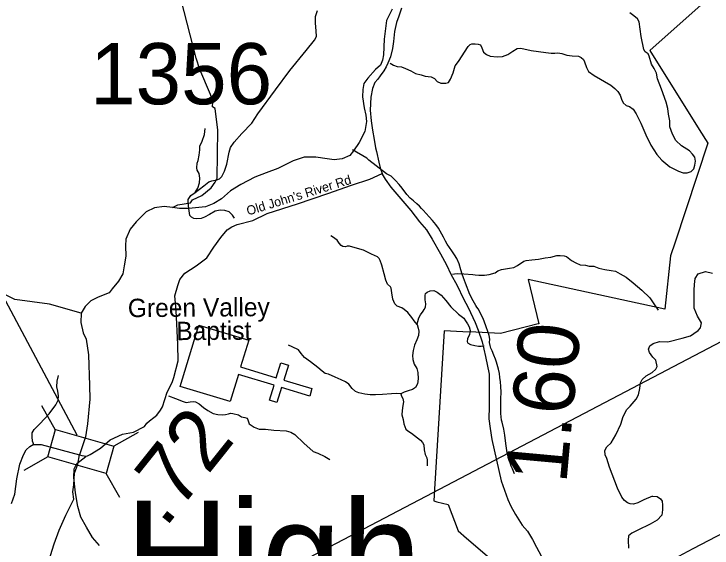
# Model space of a CAD drawing. Extents: x 1159738 to 1321356, y 736314 to 882035.
# Drawn here: x 1204145 to 1209848, y 819333 to 823694 of the extents above; entities that cross this region are included whole.
import ezdxf

# ---------------------------------------------------------------- set-up
doc = ezdxf.new("R2010")
doc.units = 0
for name, color, linetype in [('Exist Boundary Land Use Forest National US Forest Service', 7, 'Continuous'), ('Exist Cultural Church CELL', 7, 'Continuous'), ('Exist Cultural Church Label', 7, 'Continuous'), ('Exist Geographical Mountain Summit Label', 7, 'Continuous'), ('Exist Hydrographic Creek Single Shore', 7, 'Continuous'), ('Exist Hydrographic Misc Water Feature', 7, 'Continuous'), ('Exist Road Non-System Type 51', 7, 'Continuous'), ('Exist Road Primary NC Attributed', 7, 'Continuous'), ('Exist Road Primary NC Mileage Hundredths English Label', 7, 'Continuous'), ('Exist Road Secondary Mileage Hundredths English Label', 7, 'Continuous'), ('Exist Road Secondary Structure Standard Bridge CELL', 7, 'Continuous'), ('Exist Road Secondary Structure Standard Bridge Number Label', 7, 'Continuous'), ('Exist Road Secondary Type 51 Attributed', 7, 'Continuous'), ('Exist Road Secondary Type 51 Label', 7, 'Continuous'), ('Exist Road Secondary Type 51 Number Label', 7, 'Continuous')]:
    doc.layers.add(name, color=color, linetype=linetype)

msp = doc.modelspace()

# ---------------------------------------------------------------- linework, layer by layer
at = {"layer": 'Exist Boundary Land Use Forest National US Forest Service'}
for points in [[(1210716.8, 824624), (1209339.9, 823397), (1209742.6, 822750.6), (1209812.8, 822637.9), (1209546.9, 821832), (1209509.9, 821719.9), (1209462.9, 821285), (1208344.9, 821524.9), (1208432.8, 821164.9), (1208427.3, 821163.4), (1208120.8, 821084.9), (1208021.4, 821089.7), (1207917.7, 821094.8), (1207810.9, 821099.9), (1207658.9, 821107.9), (1207581.8, 819815.4), (1207575.9, 819717.9), (1207599, 819712), (1207692.9, 819687.9), (1207774.9, 819473.9), (1207843.5, 819414.6), (1208048.9, 819236.9)], [(1207696, 817082.7), (1207724.8, 817404.2), (1207856.8, 818877.8), (1208591.1, 818865.7), (1208749.2, 818863), (1208822.8, 818861.8), (1209283.9, 819106.9), (1209342.2, 819138.6), (1209612.9, 819285.9), (1209694.2, 819328.4), (1210211.4, 819598.8)]]:
    msp.add_lwpolyline(points, dxfattribs=at)
at = {"layer": 'Exist Cultural Church CELL'}
msp.add_lwpolyline([(1206062.7, 821029.8), (1205997.1, 820811.7), (1206288.6, 820723.4), (1206325.7, 820845.9), (1206386.9, 820827.4), (1206349.8, 820704.9), (1206580, 820635.1), (1206561.4, 820573.8), (1206331.2, 820643.5), (1206294.1, 820521), (1206232.9, 820539.6), (1206270, 820662.1), (1205978.5, 820750.4), (1205911.2, 820529.8), (1205503.7, 820653.3), (1205655.2, 821153.3)], close=True, dxfattribs=at)
at = {"layer": 'Exist Hydrographic Creek Single Shore'}
for points in [[(1207233.9, 823732.7), (1207188, 823640.6), (1207170.9, 823487.3), (1207164.1, 823361.2), (1207155.6, 823316.9), (1207138.6, 823276), (1207097.7, 823240.2), (1207036.4, 823168.6), (1207004, 823126), (1206995.5, 823076.6), (1206993.8, 823016.9), (1207005.7, 822926.6), (1207021.2, 822866.7), (1207026.3, 822817.3), (1207011, 822735.5), (1206966.7, 822645.1), (1206919.1, 822577), (1206888.4, 822537.8), (1206827.1, 822510.5), (1206762.4, 822502), (1206704.5, 822510.5), (1206610.8, 822524.1), (1206517.2, 822525.9), (1206425.2, 822495.2), (1206300.9, 822432.1), (1206206.6, 822396.9), (1206113, 822361.1), (1205998.9, 822301.5), (1205915.4, 822248.7), (1205840.5, 822183.9), (1205777.5, 822146.4), (1205711.1, 822119.1), (1205574.8, 822105.5)], [(1205574.8, 822105.5), (1205497, 822105.3), (1205441.8, 822115), (1205373.6, 822121.5), (1205292.4, 822111.8), (1205224.2, 822079.3), (1205143, 821998), (1205094.3, 821936.3), (1205058.6, 821855), (1205055.3, 821799.8), (1205058.6, 821715.3), (1205045.6, 821637.3), (1205035.8, 821572.3), (1205000.1, 821513.7), (1204948.1, 821448.7), (1204922.2, 821416.2), (1204834.5, 821380.5), (1204772.8, 821351.2), (1204727.3, 821305.7), (1204694.4, 821251.6), (1204691.6, 821175.7), (1204711, 821091.2), (1204735.4, 821038.4), (1204753.3, 820910), (1204761.4, 820659.7), (1204764.6, 820547.6), (1204746.7, 820347.1), (1204730.5, 820241.4), (1204681.5, 820094.2)], [(1204053.6, 819113.7), (1204147.4, 819103.5), (1204230.1, 819068.8), (1204295.3, 819079), (1204364.6, 819132), (1204413.5, 819198.9), (1204444.1, 819272.3), (1204472.6, 819368.2), (1204513.4, 819480.3), (1204570.4, 819602.7), (1204633.6, 819733.2), (1204625.4, 819793.3), (1204635.6, 819850.4), (1204639.6, 819944.2), (1204666.1, 820018.3), (1204681.5, 820094.2)]]:
    msp.add_lwpolyline(points, dxfattribs=at)
at = {"layer": 'Exist Hydrographic Misc Water Feature'}
for points in [[(1205441.8, 822115), (1205484.3, 822134.4), (1205588, 822150.8), (1205604.3, 822176.2), (1205678.9, 822212.6), (1205755.2, 822274.5), (1205789.8, 822321.8), (1205804.3, 822354.5), (1205811.6, 822745.7), (1205789.7, 822921.1), (1205766.1, 822935.7), (1205769.7, 822973.9), (1205749.7, 823037.6), (1205663.8, 823239.8), (1205632.7, 823332.3), (1205436.7, 824097.8)], [(1204694.4, 821251.6), (1204435.7, 821324.3), (1204153.8, 821362.8), (1204005.8, 821434.7), (1203729.8, 821715.9), (1203302.7, 821970.7), (1203205.7, 822058), (1203127.7, 822266.3), (1203044.8, 822612.7), (1202809.7, 822834), (1202611.7, 822923.4), (1202538.7, 823010.2), (1202508.8, 823125.7), (1202421.7, 823311.2), (1202283.7, 823740.7)], [(1208234.5, 819939.7), (1208228.9, 819953.8), (1208217.6, 819980.1), (1208208.3, 820002.4), (1208198.9, 820028.7), (1208191.5, 820048.9), (1208186, 820067.1), (1208173.1, 820109.4), (1208163.1, 820185.7), (1208155, 820256), (1208146.4, 820304.3), (1208133.9, 820360.7), (1208128.3, 820378.8), (1208121.8, 820433.1), (1208123.4, 820493), (1208123, 820551.1), (1208124.5, 820607.1), (1208121.8, 820653.2), (1208118.7, 820689.3), (1208113.8, 820725.5), (1208112.6, 820757.5), (1208103.5, 820793.8), (1208087, 820850.2), (1208077.8, 820876.5), (1208064.7, 820908.9), (1208051.4, 820943.3), (1208042.1, 820965.6), (1208034.7, 820987.8), (1208031.3, 821011.9), (1208032.1, 821039.9), (1208026.8, 821068.1), (1208019.6, 821094.3), (1208001, 821146.9), (1207978.6, 821207.4), (1207936.7, 821286.7), (1207927.1, 821300.9), (1207917.4, 821313.2), (1207896.5, 821351.8), (1207869.9, 821404.6), (1207834.4, 821495.5), (1207817.5, 821540), (1207806.3, 821570.3), (1207795.2, 821604.7), (1207782.6, 821655.1), (1207763.7, 821697.6), (1207744.6, 821728.2), (1207723.3, 821760.7), (1207704.1, 821787.3), (1207684.8, 821815.8), (1207669.4, 821840.2), (1207654.3, 821872.7), (1207612.3, 821943.8), (1207591.1, 821974.5), (1207563.9, 822007.3), (1207536.6, 822038), (1207488.2, 822091.4), (1207474.6, 822105.7), (1207459, 822124.2), (1207437.6, 822144.7), (1207410.2, 822167.5), (1207380.8, 822190.3), (1207355.6, 822219), (1207316.9, 822272.1), (1207291.7, 822302.8), (1207262.6, 822333.6), (1207246.9, 822350.1), (1207225.5, 822368.6), (1207203.8, 822381.2), (1207188, 822387.7), (1207045.4, 822499.2), (1207027.9, 822517.7), (1206911.1, 822585.3), (1206911.1, 822585.3)]]:
    msp.add_lwpolyline(points, dxfattribs=at)
at = {"layer": 'Exist Road Non-System Type 51'}
for points in [[(1205624.3, 822236.2), (1205696.8, 822289.7), (1205738.6, 822322.5), (1205762.2, 822331.6), (1205802.2, 822340.7), (1205824, 822347.9), (1205842.2, 822368), (1205864, 822409.8), (1205884, 822468), (1205902.2, 822564.5), (1205914.9, 822604.5), (1205944, 822648.1), (1206007.7, 822717.3), (1206089.5, 822802.8), (1206136.8, 822877.4), (1206281.9, 823074.6), (1206398.3, 823231.1), (1206532.8, 823396.6), (1206600.1, 823479.4), (1206616.4, 823510.4), (1206614.6, 823555.8), (1206609.1, 823617.7), (1206609.1, 823672.3), (1206625.5, 823723.2)], [(1207218.8, 823291.8), (1207245.5, 823276.2), (1207276.7, 823265), (1207310.1, 823262.8), (1207343.5, 823248.3), (1207388.1, 823230.5), (1207425.9, 823208.2), (1207472.7, 823197.1), (1207505, 823185.9), (1207552.9, 823181.5), (1207579.6, 823167), (1207603, 823143.6), (1207633.1, 823129.1), (1207673.2, 823130.2), (1207695.4, 823135.8), (1207712.1, 823161.4), (1207732.2, 823213.8), (1207750, 823269.5), (1207775.6, 823305.2), (1207856.9, 823428.9), (1207872, 823445.4), (1207885.3, 823451), (1207898.7, 823451), (1207912.1, 823451), (1207936.6, 823448.8), (1207955.5, 823443.2), (1207967.7, 823418.7), (1207981.1, 823383), (1208004.5, 823361.8), (1208036.8, 823348.5), (1208091.4, 823345.1), (1208137, 823347.4), (1208180.4, 823363), (1208219.4, 823390.8), (1208257.3, 823413.1), (1208286.2, 823414.2), (1208370.9, 823396.4), (1208490, 823378.6), (1208532.7, 823374.1), (1208563.9, 823375.2), (1208587.3, 823376.3), (1208621.8, 823370.7), (1208661.9, 823358.5), (1208706.4, 823351.8), (1208757.6, 823348.4), (1208779.9, 823339.5), (1208797.7, 823322.8), (1208806.6, 823303.9), (1208823.3, 823255.9), (1208840.1, 823223.6), (1208885.7, 823192.4), (1209021.6, 823113.3), (1209053.6, 823085.9), (1209078.1, 823061.4), (1209098.2, 823030.2), (1209108.2, 822999), (1209121.6, 822967.8), (1209146.1, 822947.7), (1209175, 822937.7), (1209204, 822916.5), (1209227.4, 822878.7), (1209267.3, 822802.3), (1209306.3, 822707.5), (1209348.6, 822623.9), (1209396.5, 822545.9), (1209437.7, 822499.1), (1209504.5, 822446.8), (1209574.6, 822410.1), (1209613.5, 822396.8), (1209645.8, 822396.8), (1209677, 822407.9), (1209698.2, 822430.2), (1209708.2, 822460.3), (1209712.6, 822492.6), (1209707.1, 822526), (1209689.3, 822548.3), (1209663.6, 822577.3), (1209597.9, 822618.5), (1209553.4, 822662), (1209525.6, 822713.3), (1209503.3, 822772.3), (1209504.4, 822821.4), (1209492.1, 822876), (1209487.7, 822921.6), (1209472.1, 822975.1), (1209434.4, 823079), (1209403.2, 823163.7), (1209393.2, 823211.6), (1209375.3, 823249.5), (1209354.2, 823284), (1209335.3, 823348.7), (1209326.3, 823369.8), (1209303, 823385.4), (1209289.6, 823404.4), (1209268.4, 823510.2), (1209252.9, 823631), (1209238.4, 823653.3), (1209209.4, 823678.9), (1209176, 823703.4)], [(1205946.1, 822027), (1205929.8, 822052.5), (1205904.3, 822077.9), (1205867.9, 822088.9), (1205829.8, 822092.5), (1205789.8, 822085.2), (1205742.5, 822057.9), (1205700.7, 822034.3), (1205673.4, 822023.4), (1205635.2, 822021.5), (1205615.2, 822023.4), (1205597, 822034.3), (1205582.5, 822048.8), (1205574.8, 822105.5), (1205569.8, 822156.2), (1205567.9, 822178), (1205589.8, 822210.8), (1205624.3, 822236.2), (1205646.1, 822272.6), (1205660.7, 822316.3), (1205662.5, 822354.5), (1205657, 822390.9), (1205642.5, 822418.2), (1205638.9, 822436.4), (1205640.7, 822474.6), (1205649.8, 822498.2), (1205658.9, 822541.9), (1205664.3, 822585.6), (1205664.3, 822614.7), (1205682.5, 822656.5), (1205700.7, 822711.1), (1205707.9, 822760.2)], [(1207439.7, 821158.9), (1207414.5, 821188.2), (1207396.3, 821215.9), (1207363.2, 821257), (1207333.9, 821282.3), (1207313.4, 821294.1), (1207274.7, 821309.2), (1207256.5, 821326.6), (1207240.7, 821364.5), (1207231.7, 821416.1), (1207227, 821454.9), (1207221.5, 821465.2), (1207196.2, 821488.9), (1207182.7, 821520.5), (1207170.9, 821572.7), (1207151.1, 821643), (1207136.9, 821681), (1207129.8, 821696.8), (1207114, 821711), (1207066.6, 821734), (1207000.4, 821764.4), (1206913.5, 821790.5), (1206886.6, 821799.2), (1206866.9, 821797.6), (1206855, 821793.6), (1206832.9, 821795.2), (1206817.9, 821804.7), (1206802.9, 821823.7), (1206785.5, 821845.8), (1206748.4, 821873.5), (1206732.6, 821883.8)], [(1207728.2, 821568.6), (1207744.5, 821573.5), (1207768.8, 821575.1), (1207819.2, 821571.9), (1207893.9, 821567), (1207911.7, 821563.8), (1207942.6, 821562.1), (1207989.7, 821562.1), (1208028.7, 821567), (1208077.4, 821580), (1208098.5, 821596.3), (1208127.7, 821607.6), (1208160.2, 821614.1), (1208194.3, 821617.4), (1208230, 821623.9), (1208259.3, 821640.1), (1208311.2, 821675.9), (1208329.1, 821682.4), (1208376.2, 821687.3), (1208431.4, 821692.1), (1208485, 821703.5), (1208530.5, 821708.4), (1208579.2, 821721.4), (1208606.8, 821723), (1208640.9, 821719.8), (1208660.4, 821714.9), (1208699.4, 821682.4), (1208735.1, 821662.9), (1208770.8, 821645), (1208813.8, 821643.3), (1208844.6, 821635.2), (1208882, 821635.2), (1208922.6, 821618.9), (1208971.3, 821607.5), (1209024.9, 821599.4), (1209059, 821594.5), (1209098, 821573.4), (1209146.7, 821545.8), (1209203.5, 821498.7), (1209273.4, 821438.5), (1209340, 821376.8), (1209377.3, 821319.9), (1209408.2, 821276)], [(1209360.5, 819756), (1209291.1, 819727.1), (1209241.6, 819702.8), (1209207.3, 819692.8), (1209179.4, 819693.7), (1209156.9, 819702.8), (1209132.5, 819720.8), (1209110, 819748.7), (1209074.9, 819823.6), (1209009.4, 819994.4), (1208987.3, 820064), (1208974.7, 820094), (1208973.1, 820128.8), (1208988.9, 820160.4), (1209023.6, 820193.6), (1209061.6, 820256.9), (1209104.2, 820343.9), (1209123.2, 820407.1), (1209153.2, 820465.6), (1209180.1, 820492.5), (1209229.1, 820549.4), (1209246.3, 820583.2), (1209258.9, 820635.4), (1209263.6, 820681.3), (1209277.9, 820709.7), (1209311.1, 820739.8), (1209358.5, 820766.6), (1209390.1, 820793.5), (1209399.5, 820815.7), (1209390.1, 820867.8), (1209363.2, 820891.6), (1209337.9, 820929.5), (1209330, 820958), (1209339.5, 820984.9), (1209366.4, 821003.8), (1209420.1, 821019.7), (1209488, 821016.5), (1209605, 821046.5), (1209672.9, 821067.1), (1209699.3, 821083.8), (1209735.6, 821109.1), (1209754.6, 821131.3), (1209760.9, 821172.4), (1209729.3, 821226.1), (1209702.5, 821292.6), (1209700.9, 821355.8), (1209700.9, 821439.6), (1209705.6, 821483.9), (1209710.4, 821534.5), (1209734.1, 821572.4), (1209794.1, 821591.4), (1209852.6, 821577.2)], [(1207439.7, 821158.9), (1207446, 821183.4), (1207453.9, 821214.2), (1207467.3, 821237.9), (1207487.1, 821267.2), (1207496.5, 821282.2), (1207508.4, 821301.2), (1207510, 821327.3), (1207505.2, 821361.3), (1207505.2, 821395.3), (1207506.8, 821411.9), (1207520.2, 821423.7), (1207546.3, 821432.4), (1207574, 821436.4), (1207602.4, 821423.7), (1207635.6, 821396.9), (1207672.7, 821354.2), (1207714.6, 821302.8), (1207775.5, 821244.3), (1207819.7, 821211.1), (1207833.9, 821188.9), (1207850.5, 821164.4), (1207864.7, 821138.3), (1207873.4, 821109.1), (1207867.1, 821077.4), (1207851.3, 821042.7), (1207848.9, 821019.7), (1207850.5, 821007.9), (1207875, 820995.2), (1207910.4, 820986), (1207938.9, 820980.5), (1207961.8, 820980.5), (1207987, 820984.4)], [(1207439.7, 821158.9), (1207447.8, 821129.8), (1207452.5, 821104.5), (1207449.4, 821069), (1207435.9, 821033.4), (1207417, 820990.7), (1207405.9, 820945.6), (1207402, 820904.5), (1207402.8, 820872.9), (1207415.4, 820835.6), (1207435.9, 820800), (1207445.4, 820765.3), (1207447, 820716.2), (1207442.2, 820675.1), (1207424.9, 820644.3), (1207401.9, 820628.5), (1207364.8, 820616.6), (1207334, 820607.1), (1207307.1, 820592.9), (1207273.5, 820595.3), (1207230.1, 820593.8), (1207156.6, 820585.8), (1207099.7, 820584.3), (1207056.2, 820583.5), (1207012, 820589.8), (1206962.2, 820601.7), (1206934.6, 820611.9), (1206909.3, 820636.4), (1206880, 820670.4), (1206854.8, 820690.2), (1206818.4, 820706), (1206768.6, 820729.7), (1206714.9, 820752.7), (1206688.1, 820759.8), (1206662.8, 820777.2), (1206626.4, 820807.2), (1206568.5, 820853.4), (1206518.7, 820889.8), (1206491.8, 820922.2), (1206468.9, 820952.2), (1206418.4, 820977.5), (1206386.8, 820990.2)], [(1204311.5, 820171.5), (1204296.9, 820205.7), (1204293.6, 820241.4), (1204295.2, 820273.9), (1204311.5, 820301.6), (1204357, 820348.7), (1204431.7, 820429.9), (1204488.5, 820501.4), (1204506.4, 820540.4), (1204508, 820576.2), (1204504.7, 820613.6), (1204495, 820649.3), (1204498.2, 820694.8), (1204509.6, 820742)], [(1205408.3, 820576.1), (1205465.2, 820555), (1205526.9, 820529), (1205552.9, 820522.5), (1205585.4, 820527.3), (1205611.3, 820529), (1205627.6, 820527.3), (1205658.4, 820511.1), (1205692.5, 820480.2), (1205728.3, 820457.5), (1205772.1, 820431.5), (1205811.1, 820423.3), (1205846.8, 820421.7), (1205874.4, 820425), (1205897.2, 820429.8), (1205913.4, 820434.7), (1205934.5, 820433.1), (1205978.4, 820421.7), (1206004.3, 820405.5), (1206030.3, 820399), (1206049.8, 820394.1), (1206056.3, 820379.5), (1206066.1, 820348.6), (1206106.7, 820320.9), (1206148.9, 820304.7), (1206199.2, 820303.1), (1206267.4, 820296.6), (1206368.1, 820290.1), (1206407.1, 820280.3), (1206441.2, 820260.8), (1206512.7, 820190.9), (1206589, 820122.7), (1206627.2, 820106.8), (1206685.6, 820080.8), (1206724.6, 820056.4)], [(1207307.1, 820592.9), (1207312.3, 820572.4), (1207321.8, 820553.4), (1207326.5, 820526.5), (1207321.8, 820496.5), (1207315.4, 820456.9), (1207313.9, 820422.1), (1207324.9, 820382.6), (1207331.2, 820347.8), (1207345.5, 820303.5), (1207362.9, 820289.3), (1207392.9, 820271.9), (1207465.6, 820213.4), (1207482.9, 820194.4), (1207492.4, 820177), (1207497.2, 820134.3), (1207503.5, 820096.4), (1207517.7, 820071.1), (1207520.9, 820052.1), (1207520.9, 820004.7)], [(1204845.4, 819352.8), (1204787.9, 819419.1), (1204737.3, 819502.7), (1204690.3, 819584.7), (1204667.7, 819671.8), (1204646.8, 819785.2), (1204634.6, 819908.9), (1204636.3, 819979.4), (1204659, 820024.7), (1204733.6, 820080)], [(1209360.5, 819756), (1209399.2, 819754.5), (1209428, 819736.5), (1209440.6, 819716.7), (1209444.2, 819684.2), (1209444.2, 819644.5), (1209437, 819601.3), (1209401, 819561.6), (1209341.5, 819529.1), (1209242.4, 819480.4), (1209192, 819455.2), (1209164.9, 819433.5), (1209163.1, 819397.5), (1209166.7, 819332.5)]]:
    msp.add_lwpolyline(points, dxfattribs=at)
at = {"layer": 'Exist Road Primary NC Attributed'}
for points in [[(1207311.8, 823740.1), (1207288.7, 823676.6), (1207269.6, 823625.3), (1207254.1, 823550.8), (1207246.7, 823468.9), (1207237.6, 823411.6), (1207222.4, 823343.9), (1207199.3, 823291.7), (1207186.7, 823262.6), (1207166.3, 823228.6), (1207137.5, 823189.7)], [(1207137.5, 823189.7), (1207116.9, 823161.3), (1207094.3, 823134), (1207075.6, 823086.7), (1207060.1, 823014.8), (1207054.2, 822909), (1207062.5, 822822.6), (1207074.9, 822744.5), (1207087.4, 822667.9), (1207098.3, 822602), (1207107.7, 822571.6), (1207126, 822485), (1207137.2, 822438.7), (1207152.1, 822390.8)], [(1207152.1, 822390.8), (1207154.6, 822386.8), (1207177.4, 822346.1), (1207224.1, 822279.5), (1207290.6, 822204.3), (1207386.4, 822088.4), (1207458.6, 821996.7), (1207515.3, 821931.5), (1207563, 821855.4), (1207629.9, 821735), (1207678.4, 821644.7), (1207715.1, 821569.4), (1207765.3, 821475.7), (1207817.1, 821368.7), (1207855.5, 821296.7), (1207912.3, 821175.2), (1207937.4, 821113.3), (1207969.1, 821016.3), (1207997.5, 820897.6), (1208027.6, 820752.7), (1208027.6, 820488.4), (1208024.2, 820387.2), (1208035.9, 820310.2), (1208049.3, 820219.9), (1208126.2, 819882.7), (1208179.6, 819730.5), (1208204.7, 819675.3), (1208241.5, 819608.4), (1208296.4, 819520.6), (1208339.9, 819472.1), (1208381.6, 819401.8), (1208415.1, 819341.6), (1208451.8, 819269.7)]]:
    msp.add_lwpolyline(points, dxfattribs=at)
at = {"layer": 'Exist Road Secondary Structure Standard Bridge CELL'}
for p, q in [((1204483.9, 820296.1), (1204373.4, 820493.6)), ((1205159.6, 820275.5), (1204962.1, 820165.1)), ((1204422.3, 820078.2), (1204224.7, 819967.8)), ((1205009.5, 819744.7), (1204899, 819942.3))]:
    msp.add_line(p, q, dxfattribs=at)
msp.add_lwpolyline([(1204899, 819942.3), (1204422, 820077.2), (1204485, 820300), (1204962.1, 820165.1)], close=True, dxfattribs=at)
at = {"layer": 'Exist Road Secondary Structure Standard Bridge Number Label'}
for p, q in [((1204661, 820254.4), (1201694, 825817.5)), ((1197975.4, 814760.2), (1210182.3, 821156.6))]:
    msp.add_line(p, q, dxfattribs=at)
at = {"layer": 'Exist Road Secondary Type 51 Attributed'}
for points in [[(1204681.5, 820094.2), (1204700.4, 820089.6), (1204741.2, 820083.9), (1204768, 820097.3), (1204853.2, 820148), (1204931.6, 820217.7), (1205030.9, 820263), (1205121.5, 820278.7), (1205210.4, 820325.8), (1205231.3, 820351.9), (1205253, 820372.4), (1205287.3, 820397.9), (1205311.7, 820418.8), (1205342.5, 820458.4), (1205358.1, 820487.2), (1205397, 820605.1), (1205437.2, 820685.4), (1205450.5, 820725.5), (1205486.8, 820861.2), (1205483.5, 820995), (1205470.1, 821272.7), (1205460.1, 821393.1), (1205483.5, 821476.7), (1205500.2, 821526.9), (1205540.3, 821577.1), (1205633.9, 821637.3), (1205720.8, 821704.2), (1205777.6, 821791.2), (1205834.5, 821868.1), (1205887.9, 821931.7), (1205924.8, 821956), (1205968.2, 821975.2), (1206097.5, 822007.4), (1206214.5, 822064.2), (1206461.9, 822144.5), (1206709.3, 822228.1), (1206903.2, 822295.1), (1207053.6, 822345.2), (1207152.1, 822390.8)], [(1204124, 819697.1), (1204151.9, 819772.1), (1204169.3, 819897.6), (1204193.7, 820017.9), (1204223.2, 820093.9), (1204244.1, 820135.7), (1204275.5, 820163.6), (1204303.4, 820177.6), (1204367.8, 820179.3), (1204681.5, 820094.2)]]:
    msp.add_lwpolyline(points, dxfattribs=at)

# ---------------------------------------------------------------- texts
at = {"layer": 'Exist Cultural Church Label'}
for s, p in [('Green Valley', (1205076.2, 821218.4)), ('Baptist', (1205471.5, 821030.3))]:
    msp.add_text(s, height=150, rotation=0.4217, dxfattribs=at).set_placement(p)
at = {"layer": 'Exist Geographical Mountain Summit Label'}
msp.add_text('High', height=880, dxfattribs=at).set_placement((1205054.8, 818840.4))
at = {"layer": 'Exist Road Primary NC Mileage Hundredths English Label'}
msp.add_text('1.60', height=500, rotation=84.7737, dxfattribs=at).set_placement((1208657.4, 819852.2))
at = {"layer": 'Exist Road Secondary Mileage Hundredths English Label'}
msp.add_text('.72', height=500, rotation=51.3603, dxfattribs=at).set_placement((1205379.1, 819489.6))
at = {"layer": 'Exist Road Secondary Type 51 Label'}
msp.add_text("Old John's River Rd", height=75, rotation=17.1365, dxfattribs=at).set_placement((1206058.3, 822047.6))
at = {"layer": 'Exist Road Secondary Type 51 Number Label'}
msp.add_text('1356', height=500, dxfattribs=at).set_placement((1204767.1, 822956.5))

doc.saveas('drawing.dxf')
